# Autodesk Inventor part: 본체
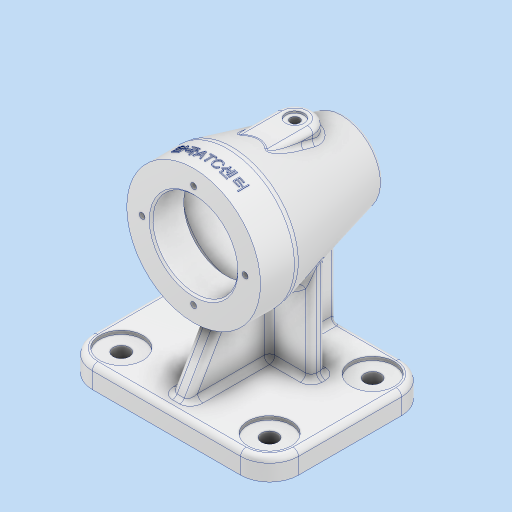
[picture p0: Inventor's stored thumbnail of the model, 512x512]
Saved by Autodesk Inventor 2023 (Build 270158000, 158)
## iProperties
Created: 2024-12
Part Number: 본체
Material: 알루미늄 6061
Document SubType Name: Modeling
Designer: asung
Density: 2.7 g/cm^3
Appearance: 알루미늄 - 평지
Author: asung
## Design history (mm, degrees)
sketch "스케치1"
  geometry: L1 (41, -44.5)-(-41, -44.5); L2 (-57, -28.5)-(-57, 28.5); L3 (-41, 44.5)-(41, 44.5); L4 (57, 28.5)-(57, -28.5); L5 (57, -44.5)-(-57, 44.5); L6 (-57, -44.5)-(57, 44.5); A1 r 16 centre (41, -28.5) between (41, -44.5) and (57, -28.5); A2 r 16 centre (41, 28.5) between (57, 28.5) and (41, 44.5); A3 r 16 centre (-41, 28.5) between (-41, 44.5) and (-57, 28.5); A4 r 16 centre (-41, -28.5) between (-57, -28.5) and (-41, -44.5); 1 further point
  constraints: 12 end point, 8 point on circle, 8 point on line, 8 tangent, 4 centre point, 3 equal radius, 2 midpoint, 2 parallel, 1 horizontal, 1 perpendicular
  dimensions: "d0" = 114 distance of L5.end L6.end; "d1" = 89 distance of L6.start L5.end; "d2" = 16 radius of A1
extrude "돌출1" new body sketch "스케치1" distance "d3" = 12; taper "d4" = 0 deg
fillet "모깎기1" dims "d5" = 3
sketch "스케치2"
  geometry: A1 r 16 centre (-41, 28.5) between (-41, 44.5) and (-57, 28.5) reference; A2 r 16 centre (41, 28.5) between (57, 28.5) and (41, 44.5) reference; A3 r 16 centre (-41, -28.5) between (-57, -28.5) and (-41, -44.5) reference; A4 r 16 centre (41, -28.5) between (41, -44.5) and (57, -28.5) reference; 5 further points
  constraints: 4 coincident
hole "구멍1" sketch "스케치2" at (-41, 28.5), (41, 28.5), (-41, -28.5), (41, -28.5) diameter "d6" = 9; stored, may be unused: countersink angle "d10" = 90 deg, drill point angle "d12" = 0 deg; dims "d7" = 6, "d8" = 24, "d9" = 2, "d11" = 12
node "작업 평면1"
sketch "스케치3"
  geometry: L1 (9, -44.5)-(0, -44.5) reference; L2 (0, -44.5)-(0, 44.5) reference; L3 (0, 44.5)-(9, 44.5) reference; L4 (12, 41.5)-(12, -41.5) reference; L5 (9, -44.5)-(0, -44.5) reference; L6 (0, -44.5)-(0, 44.5) reference; L7 (0, 44.5)-(9, 44.5) reference; L8 (12, 41.5)-(12, -41.5) reference; L9 (9, -44.5)-(0, -44.5) reference; L10 (0, -44.5)-(0, 44.5) reference; L11 (0, 44.5)-(9, 44.5) reference; L12 (12, 41.5)-(12, -41.5) reference; L13 (0, 44.5)-(82, 44.5); L14 (82, 44.5)-(82, 29.5); L15 (82, 29.5)-(82, -54.5); L16 (119, 29.5)-(45, 29.5); L17 (103, -54.5)-(61, -54.5); L18 (119, 29.5)-(119, 9.5); L19 (119, 9.5)-(103, -54.5); A1 r 3 centre (9, -41.5) between (9, -44.5) and (12, -41.5) reference; A2 r 3 centre (9, 41.5) between (12, 41.5) and (9, 44.5) reference; A3 r 3 centre (9, -41.5) between (9, -44.5) and (12, -41.5) reference; A4 r 3 centre (9, 41.5) between (12, 41.5) and (9, 44.5) reference; A5 r 3 centre (9, -41.5) between (9, -44.5) and (12, -41.5) reference; A6 r 3 centre (9, 41.5) between (12, 41.5) and (9, 44.5) reference; 1 further point
  constraints: 14 end point, 3 horizontal, 2 midpoint, 2 vertical, 1 perpendicular
  dimensions: "d14" = 82 distance of L2.end L13.end; "d15" = 15 distance of L14.end L13.end; "d16" = 84 distance of L14.end L15.end; "d17" = 74 distance of L16.start L16.end; "d18" = 42 distance of L17.start L17.end; "d19" = 20 distance of L16.start L18.end
revolve "회전1" sketch "스케치3" stored, may be unused: angle "d20" = 90 deg
fillet "모깎기2" dims "d21" = 10
sketch "스케치4"
  geometry: L1 through (9, -44.5) direction (-1, 0) reference; L2 through (0, 44.5) direction (1, 9.87e-16) reference; L3 through (12, 41.5) direction (0, -1) reference; L4 through (9, -44.5) direction (-1, 0) reference; L5 through (0, 44.5) direction (1, 9.87e-16) reference; L6 through (12, 41.5) direction (0, -1) reference; L7 through (45, 10.731) direction (0, 1) reference; L8 through (45, 29.5) direction (1, 2.4e-16) reference; L9 through (119, 29.5) direction (0, -1) reference; L10 through (9, -44.5) direction (-1, 0) reference; L11 through (0, 44.5) direction (1, 9.87e-16) reference; L12 through (12, 41.5) direction (0, -1) reference; L13 through (45, 10.731) direction (0, 1) reference; L14 through (45, 29.5) direction (1, 2.4e-16) reference; L15 through (119, 29.5) direction (0, -1) reference; L16 through (9, -44.5) direction (-1, 0) reference; L17 through (0, 44.5) direction (1, 9.87e-16) reference; L18 through (12, 41.5) direction (0, -1) reference; L19 through (45, 10.731) direction (0, 1) reference; L20 through (45, 29.5) direction (1, 2.4e-16) reference; L21 through (119, 29.5) direction (0, -1) reference; L22 through (9, -44.5) direction (-1, 0) reference; L23 through (0, 44.5) direction (1, 9.87e-16) reference; L24 through (12, 41.5) direction (0, -1) reference; L25 through (45, 10.731) direction (0, 1) reference; L26 through (45, 29.5) direction (1, 2.4e-16) reference; L27 through (119, 29.5) direction (0, -1) reference; L28 through (9, -44.5) direction (-1, 0) reference; L29 through (0, 44.5) direction (1, 9.87e-16) reference; L30 through (12, 41.5) direction (0, -1) reference; L31 through (45, 10.731) direction (0, 1) reference; L32 through (45, 29.5) direction (1, 2.4e-16) reference; L33 (82, 29.5)-(82, -54.5); L34 (105.5, 29.5)-(105.5, 11.5); L35 (105.5, 11.5)-(107.942, 11.5); L36 (112.793, 5.287)-(103.664, -31.228); L37 (100.754, -33.5)-(99.5, -33.5); L38 (99.5, -33.5)-(99.5, -43.2); L39 (99.2, -43.5)-(97.5, -43.5); L40 (95.914, -43.5)-(95.914, -43.5); L41 (94.5, -46.5)-(82, -46.5); L42 (97.5, -43.5)-(97.5, -43.5); L43 through (9, -44.5) direction (-1, 0) reference; L44 through (0, 44.5) direction (1, 9.87e-16) reference; L45 through (12, 41.5) direction (0, -1) reference; L46 through (45, 10.731) direction (0, 1) reference; L47 through (119, 29.5) direction (0, -1) reference; L48 through (9, -44.5) direction (-1, 0) reference; L49 through (0, 44.5) direction (1, 9.87e-16) reference; L50 through (12, 41.5) direction (0, -1) reference; L51 through (45, 10.731) direction (0, 1) reference; L52 through (119, 29.5) direction (0, -1) reference; L53 through (9, -44.5) direction (-1, 0) reference; L54 through (0, 44.5) direction (1, 9.87e-16) reference; L55 through (12, 41.5) direction (0, -1) reference; L56 through (45, 10.731) direction (0, 1) reference; L57 through (119, 29.5) direction (0, -1) reference; L58 through (9, -44.5) direction (-1, 0) reference; L59 through (0, 44.5) direction (1, 9.87e-16) reference; L60 through (12, 41.5) direction (0, -1) reference; L61 through (45, 10.731) direction (0, 1) reference; L62 through (119, 29.5) direction (0, -1) reference; L63 through (9, -44.5) direction (-1, 0) reference; L64 through (0, 44.5) direction (1, 9.87e-16) reference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; A1 r 10 centre (109, 10.731) between (118.701, 8.306) and (119, 10.731) reference; A2 r 10 centre (55, 10.731) between (45, 10.731) and (45.299, 8.306) reference; A3 r 5 centre (107.942, 6.5) between (112.793, 5.287) and (107.942, 11.5); A4 r 3 centre (100.754, -30.5) between (100.754, -33.5) and (103.664, -31.228); A5 r 0.3 centre (99.2, -43.2) between (99.2, -43.5) and (99.5, -43.2); A6 r 3 centre (94.5, -43.5) between (94.5, -46.5) and (97.5, -43.5); A7 r 10 centre (109, 10.731) between (118.701, 8.306) and (119, 10.731) reference; A8 r 10 centre (55, 10.731) between (45, 10.731) and (45.299, 8.306) reference; A9 r 10 centre (109, 10.731) between (118.701, 8.306) and (119, 10.731) reference; A10 r 10 centre (55, 10.731) between (45, 10.731) and (45.299, 8.306) reference; A11 r 10 centre (109, 10.731) between (118.701, 8.306) and (119, 10.731) reference; A12 r 10 centre (55, 10.731) between (45, 10.731) and (45.299, 8.306) reference; A13 r 10 centre (109, 10.731) between (118.701, 8.306) and (119, 10.731) reference; A14 r 10 centre (55, 10.731) between (45, 10.731) and (45.299, 8.306) reference; A15 r 10 centre (109, 10.731) between (118.701, 8.306) and (119, 10.731) reference; A16 r 10 centre (55, 10.731) between (45, 10.731) and (45.299, 8.306) reference; A17 r 10 centre (109, 10.731) between (118.701, 8.306) and (119, 10.731) reference; A18 r 10 centre (55, 10.731) between (45, 10.731) and (45.299, 8.306) reference; A19 r 10 centre (109, 10.731) between (118.701, 8.306) and (119, 10.731) reference; A20 r 10 centre (55, 10.731) between (45, 10.731) and (45.299, 8.306) reference; A21 r 10 centre (109, 10.731) between (118.701, 8.306) and (119, 10.731) reference; A22 r 10 centre (55, 10.731) between (45, 10.731) and (45.299, 8.306) reference; A23 r 10 centre (109, 10.731) between (118.701, 8.306) and (119, 10.731) reference; A24 r 10 centre (55, 10.731) between (45, 10.731) and (45.299, 8.306) reference; A25 r 10 centre (109, 10.731) between (118.701, 8.306) and (119, 10.731) reference; A26 r 10 centre (55, 10.731) between (45, 10.731) and (45.299, 8.306) reference; A27 r 10 centre (109, 10.731) between (118.701, 8.306) and (119, 10.731) reference; A28 r 10 centre (55, 10.731) between (45, 10.731) and (45.299, 8.306) reference; A29 r 10 centre (109, 10.731) between (118.701, 8.306) and (119, 10.731) reference; A30 r 10 centre (55, 10.731) between (45, 10.731) and (45.299, 8.306) reference; 31 further points; 64 other entities
  constraints: 20 end point, 9 point on line, 8 horizontal alignment, 8 point on circle, 8 tangent, 6 perpendicular, 4 centre point, 3 coincident, 1 horizontal, 1 vertical, 90 other
  dimensions: "d22" = 5 dimension on L36; "d23" = 47 diameter of L34 L33; "d24" = 18 dimension on L35; "d25" = 45 vertical distance of point (114.346, 11.5) point (103.096, -33.5); "d26" = 10 distance of L37.end point (99.5, -43.5); "d28" = 5 radius of A3; "d29" = 3 radius of A4; "d30" = 0.3 radius of A5; "d31" = 35 diameter of L38 L33; "d33" = 31 diameter of L42 L33; "d34" = 3 distance between parallel lines of L39 L41; "d35" = 3 radius of A6 (derived)
  node "절단 모서리 투영4"
  node "절단 모서리 투영5"
  node "절단 모서리 투영6"
  node "절단 모서리 투영7"
  node "절단 모서리 투영8"
  node "절단 모서리 투영9"
  node "절단 모서리 투영10"
  node "절단 모서리 투영11"
  node "절단 모서리 투영12"
  node "절단 모서리 투영13"
  node "절단 모서리 투영14"
  node "절단 모서리 투영15"
  node "절단 모서리 투영16"
revolve "회전2" stored, may be unused: angle "d37" = 90 deg
chamfer "모따기1" distance "d38" = 1; stored, may be unused: second distance "d39" = 2, angle "d40" = 45 deg
chamfer "모따기2" distance "d41" = 1; stored, may be unused: second distance "d42" = 2, angle "d43" = 45 deg
node "작업 평면2"
sketch "스케치5"
  geometry: L1 (24.5, 29.5)-(-24.5, 29.5) reference; L2 (0, 29.5)-(0, -26.5); L3 (10, 29.5)-(10, -26.5); L4 (-10, 29.5)-(-10, -26.5); L5 (-16.733, 10.731)-(-16.733, 29.5) reference; L6 (-16.733, 29.5)-(16.733, 29.5) reference; L7 (16.733, 29.5)-(16.733, 10.731) reference; L8 (-10, 29.5)-(10, 29.5); L9 (-16.733, 10.731)-(-16.733, 29.5) reference; L10 (-16.733, 29.5)-(16.733, 29.5) reference; L11 (16.733, 29.5)-(16.733, 10.731) reference; L12 (-16.733, 10.731)-(-16.733, 29.5) reference; L13 (-16.733, 29.5)-(16.733, 29.5) reference; L14 (16.733, 29.5)-(16.733, 10.731) reference; L15 (36.701, 8.306)-(-36.701, 8.306) reference; L16 (30.793, 5.287)-(-30.793, 5.287) reference; C1 r 10 at (0, -26.5); 9 further points
  constraints: 8 end point, 2 parallel, 1 centre point, 1 coincident, 1 collinear, 1 horizontal alignment, 1 midpoint, 1 vertical, 8 other
  dimensions: "d45" = 56 distance of L2.start L2.end; "d46" = 20 diameter of C1; "d47" = 10 distance between parallel lines of L2 L3; "d48" = 10 distance between parallel lines of L2 L4; "d49" = 0 distance between parallel lines of L8 L1; "d50" = 56 distance from line of L3.end L1; "d51" = 56 distance from line of L4.end L1
extrude "돌출2" join sketch "스케치5" distance "d52" = 8; taper "d53" = 0 deg
revolve "회전3" stored, may be unused: angle "d55" = 90 deg
sketch "스케치6"
  geometry: A1 r 10 centre (0, 26.5) between (10, 26.5) and (-10, 26.5) reference; 2 further points
  constraints: 1 coincident
hole "구멍2" sketch "스케치6" at (0, 26.5) diameter "d56" = 5.1881; stored, may be unused: countersink angle "d60" = 90 deg, drill point angle "d62" = 118 deg; dims "d57" = 20, "d58" = 10, "d59" = 1, "d61" = 20
fillet "모깎기3" dims "d63" = 3
fillet "모깎기4" dims "d64" = 3
sketch "스케치7"
  geometry: L1 (-28, 15.5)-(28, 15.5); L2 (28, 15.5)-(28, 7.5); L3 (28, 7.5)-(-28, 7.5); L4 (-28, 7.5)-(-28, 15.5); L5 (41, 44.5)-(-41, 44.5) reference; L6 (0, 44.5)-(0, 15.5); 1 further point
  constraints: 10 end point, 2 midpoint, 2 parallel, 1 horizontal, 1 perpendicular, 1 vertical
  dimensions: "d65" = 56 distance of L2.end L3.end; "d66" = 8 distance of L1.end L2.end; "d67" = 29 distance of L6.end L6.start
extrude "돌출3" join sketch "스케치7" stored distance "d68" = 8; taper "d69" = 0 deg
sketch "스케치8"
  geometry: L1 (105.5, 28.5)-(106.5, 29.5) reference; L2 (106.5, 29.5)-(119, 29.5) reference; L3 (119, 29.5)-(119, 10.731) reference; L4 (118.701, 8.306)-(115.09, -6.142) reference; L5 (115, -6.869)-(115, -21.5) reference; L6 (115, -21.5)-(114, -21.5) reference; L7 (114, -21.5)-(114, -23.906) reference; L8 (114, -23.906)-(105.495, -23.906) reference; L9 (105.495, -23.906)-(112.793, 5.287) reference; L10 (107.942, 11.5)-(105.5, 11.5) reference; L11 (105.5, 11.5)-(105.5, 28.5) reference; L12 (69.5, -46.5)-(94.5, -46.5) reference; L13 (97.5, -43.5)-(99.2, -43.5) reference; L14 (99.5, -43.2)-(99.5, -34.5) reference; L15 (99.5, -34.5)-(100.5, -33.5) reference; L16 (100.5, -33.5)-(100.754, -33.5) reference; L17 (103.664, -31.228)-(104.198, -29.094) reference; L18 (104.198, -29.094)-(114, -29.094) reference; L19 (114, -29.094)-(114, -31.5) reference; L20 (114, -31.5)-(115, -31.5) reference; L21 (115, -31.5)-(115, -33.5) reference; L22 (112, -36.5)-(109.842, -36.5) reference; L23 (106.932, -38.772)-(103, -54.5) reference; L24 (61, -54.5)-(51.25, -15.5) reference; L25 (51.25, -15.5)-(12, -15.5) reference; L26 (12, -15.5)-(12, -41.5) reference; L27 (9, -44.5)-(0, -44.5) reference; L28 (0, -44.5)-(0, 44.5) reference; L29 (0, 44.5)-(9, 44.5) reference; L30 (12, 41.5)-(12, -7.5) reference; L31 (12, -7.5)-(49.25, -7.5) reference; L32 (49.25, -7.5)-(45.299, 8.306) reference; L33 (45, 10.731)-(45, 29.5) reference; L34 (45, 29.5)-(57.5, 29.5) reference; L35 (57.5, 29.5)-(58.5, 28.5) reference; L36 (58.5, 28.5)-(58.5, 11.5) reference; L37 (58.5, 11.5)-(56.058, 11.5) reference; L38 (51.207, 5.287)-(60.336, -31.228) reference; L39 (63.246, -33.5)-(63.5, -33.5) reference; L40 (63.5, -33.5)-(64.5, -34.5) reference; L41 (64.5, -34.5)-(64.5, -43.2) reference; L42 (64.8, -43.5)-(66.5, -43.5) reference; L43 (105.5, 28.5)-(106.5, 29.5) reference; L44 (106.5, 29.5)-(119, 29.5) reference; L45 (119, 29.5)-(119, 10.731) reference; L46 (118.701, 8.306)-(115.09, -6.142) reference; L47 (115, -6.869)-(115, -21.5) reference; L48 (115, -21.5)-(114, -21.5) reference; L49 (114, -21.5)-(114, -23.906) reference; L50 (114, -23.906)-(105.495, -23.906) reference; L51 (105.495, -23.906)-(112.793, 5.287) reference; L52 (107.942, 11.5)-(105.5, 11.5) reference; L53 (105.5, 11.5)-(105.5, 28.5) reference; L54 (69.5, -46.5)-(94.5, -46.5) reference; L55 (97.5, -43.5)-(99.2, -43.5) reference; L56 (99.5, -43.2)-(99.5, -34.5) reference; L57 (99.5, -34.5)-(100.5, -33.5) reference; L58 (100.5, -33.5)-(100.754, -33.5) reference; L59 (103.664, -31.228)-(104.198, -29.094) reference; L60 (104.198, -29.094)-(114, -29.094) reference; L61 (114, -29.094)-(114, -31.5) reference; L62 (114, -31.5)-(115, -31.5) reference; L63 (115, -31.5)-(115, -33.5) reference; L64 (112, -36.5)-(109.842, -36.5) reference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; A1 r 10 centre (109, 10.731) between (118.701, 8.306) and (119, 10.731) reference; A2 r 5 centre (107.942, 6.5) between (112.793, 5.287) and (107.942, 11.5) reference; A3 r 3 centre (94.5, -43.5) between (94.5, -46.5) and (97.5, -43.5) reference; A4 r 0.3 centre (99.2, -43.2) between (99.2, -43.5) and (99.5, -43.2) reference; A5 r 3 centre (100.754, -30.5) between (100.754, -33.5) and (103.664, -31.228) reference; A6 r 3 centre (112, -33.5) between (112, -36.5) and (115, -33.5) reference; A7 r 3 centre (9, -41.5) between (9, -44.5) and (12, -41.5) reference; A8 r 3 centre (9, 41.5) between (12, 41.5) and (9, 44.5) reference; A9 r 10 centre (55, 10.731) between (45, 10.731) and (45.299, 8.306) reference; A10 r 5 centre (56.058, 6.5) between (56.058, 11.5) and (51.207, 5.287) reference; A11 r 3 centre (63.246, -30.5) between (60.336, -31.228) and (63.246, -33.5) reference; A12 r 0.3 centre (64.8, -43.2) between (64.5, -43.2) and (64.8, -43.5) reference; A13 r 3 centre (69.5, -43.5) between (66.5, -43.5) and (69.5, -46.5) reference; A14 r 5 centre (107.942, 6.5) between (112.793, 5.287) and (107.942, 11.5) reference; A15 r 3 centre (94.5, -43.5) between (94.5, -46.5) and (97.5, -43.5) reference; A16 r 0.3 centre (99.2, -43.2) between (99.2, -43.5) and (99.5, -43.2) reference; A17 r 3 centre (100.754, -30.5) between (100.754, -33.5) and (103.664, -31.228) reference; A18 r 3 centre (112, -33.5) between (112, -36.5) and (115, -33.5) reference; A19 r 3 centre (9, -41.5) between (9, -44.5) and (12, -41.5) reference; A20 r 3 centre (9, 41.5) between (12, 41.5) and (9, 44.5) reference; A21 r 5 centre (56.058, 6.5) between (56.058, 11.5) and (51.207, 5.287) reference; A22 r 3 centre (63.246, -30.5) between (60.336, -31.228) and (63.246, -33.5) reference; A23 r 0.3 centre (64.8, -43.2) between (64.5, -43.2) and (64.8, -43.5) reference; A24 r 3 centre (69.5, -43.5) between (66.5, -43.5) and (69.5, -46.5) reference; A25 r 5 centre (107.942, 6.5) between (112.793, 5.287) and (107.942, 11.5) reference; A26 r 3 centre (94.5, -43.5) between (94.5, -46.5) and (97.5, -43.5) reference; A27 r 0.3 centre (99.2, -43.2) between (99.2, -43.5) and (99.5, -43.2) reference; A28 r 3 centre (100.754, -30.5) between (100.754, -33.5) and (103.664, -31.228) reference; A29 r 3 centre (112, -33.5) between (112, -36.5) and (115, -33.5) reference; A30 r 3 centre (9, -41.5) between (9, -44.5) and (12, -41.5) reference; A31 r 3 centre (9, 41.5) between (12, 41.5) and (9, 44.5) reference; A32 r 5 centre (56.058, 6.5) between (56.058, 11.5) and (51.207, 5.287) reference; A33 r 3 centre (63.246, -30.5) between (60.336, -31.228) and (63.246, -33.5) reference; A34 r 0.3 centre (64.8, -43.2) between (64.5, -43.2) and (64.8, -43.5) reference; A35 r 3 centre (69.5, -43.5) between (66.5, -43.5) and (69.5, -46.5) reference; A36 r 10 centre (109, 10.731) between (118.701, 8.306) and (119, 10.731) reference; A37 r 10 centre (55, 10.731) between (45, 10.731) and (45.299, 8.306) reference; A38 r 10 centre (109, 10.731) between (118.701, 8.306) and (119, 10.731) reference; A39 r 10 centre (55, 10.731) between (45, 10.731) and (45.299, 8.306) reference; 1 further point
  constraints: 4 end point, 3 point on line, 1 horizontal, 6 other
  dimensions: "d70" = 7 distance from line of L29 L129.end; "d71" = 60 deg angle of L30 L129
  node "절단 모서리 투영20"
  node "절단 모서리 투영21"
  node "절단 모서리 투영22"
feature "리브1" dims "d72" = 1, "d73" = 10, "d74" = 0, "d75" = 0, "d76" = 1, "d77" = 1
feature "리브2" dims "d78" = 1, "d79" = 10, "d80" = 0, "d81" = 0, "d82" = 1, "d83" = 1
fillet "모깎기5" dims "d84" = 3
fillet "모깎기6" dims "d85" = 3
sketch "스케치9"
  geometry: L1 (-52.958, -72)-(-45.387, -72) reference; L2 (-45.387, -72)-(-45.387, -82) reference; L3 (-45.387, -82)-(-56.969, -82) reference; L4 (-56.969, -82)-(-56.969, -73) reference; L5 (-53.961, -70)-(-52.958, -70) reference; L6 (-52.958, -70)-(-52.958, -72) reference; L7 (29.042, -72)-(36.613, -72) reference; L8 (36.613, -72)-(36.613, -82) reference; L9 (36.613, -82)-(-36.613, -82) reference; L10 (-36.613, -82)-(-36.613, -72) reference; L11 (-36.613, -72)-(-29.042, -72) reference; L12 (-29.042, -72)-(-29.042, -70) reference; L13 (-29.042, -70)-(-8, -70) reference; L14 (-5, -67)-(-5, -62.144) reference; L15 (-2, -56.144)-(2, -56.144) reference; L16 (5, -62.144)-(5, -67) reference; L17 (8, -70)-(29.042, -70) reference; L18 (29.042, -70)-(29.042, -72) reference; L19 (45.387, -72)-(52.958, -72) reference; L20 (52.958, -72)-(52.958, -70) reference; L21 (52.958, -70)-(53.961, -70) reference; L22 (56.969, -73)-(56.969, -82) reference; L23 (56.969, -82)-(45.387, -82) reference; L24 (45.387, -82)-(45.387, -72) reference; C1 r 37 at (0, 0) reference; C2 r 37 at (0, 0) reference; C3 r 24.5 at (0, 0) reference; A1 r 3 centre (-8, -67) between (-8, -70) and (-5, -67) reference; A2 r 3 centre (8, -67) between (5, -67) and (8, -70) reference; A3 r 28.5 centre (0, 0) between (0, 28.5) and (-28.5, 0); 5 further points; 2 other entities
  constraints: 4 point on circle, 2 horizontal alignment, 2 vertical alignment, 1 centre point, 1 coincident, 4 other
  dimensions: "d86" = 57 diameter of A3
  node "절단 모서리 투영23"
node "작업 평면3"
sketch "스케치10"
  geometry: L1 (-37, 10)-(37, 10) reference; 2 further points
  constraints: 1 vertical alignment, 1 other
  dimensions: "d87" = 9 distance from line of L1 point (0, 1)
feature "엠보싱1" sketch "스케치10" dims "d0" = 114, "d1" = 89, "d2" = 16, "d88" = 0.5, "d89" = 0
hole "구멍3" sketch "스케치9" diameter "d90" = 3.242; stored, may be unused: countersink angle "d94" = 90 deg, drill point angle "d96" = 118 deg; dims "d91" = 8, "d92" = 4, "d93" = 2, "d95" = 10
fillet "모깎기7" dims "d97" = 3
feature "ץ耀ק耀ש耀׫耀׭耀ׯ耀ױ耀׳耀" dims "d0" = 114, "d1" = 89, "d2" = 16, "d3" = 12, "d4" = 0, "d5" = 3, "d6" = 9, "d7" = 6, "d8" = 24, "d9" = 2, "d10" = 90 deg, "d11" = 12, "d12" = 0, "d13" = -15, "d14" = 82, "d15" = 15, "d16" = 84, "d17" = 74, "d18" = 42, "d19" = 20, "d20" = 90 deg, "d21" = 10, "d22" = 5, "d23" = 47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
node "솔리드1"
node "투영된 루프1"
node "절단 모서리 투영1"
node "절단 모서리 투영2"
node "절단 모서리 투영3"
node "절단 모서리 투영17"
node "절단 모서리 투영18"
node "절단 모서리 투영19"
feature "A9D066F2-1C7D-4E18-AEED-F7BC21143FA4" dims "d6" = 9, "d7" = 6, "d8" = 24, "d9" = 2, "d10" = 90 deg, "d11" = 12, "d12" = 0
